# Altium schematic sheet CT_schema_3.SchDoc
size 283 x 147 mm
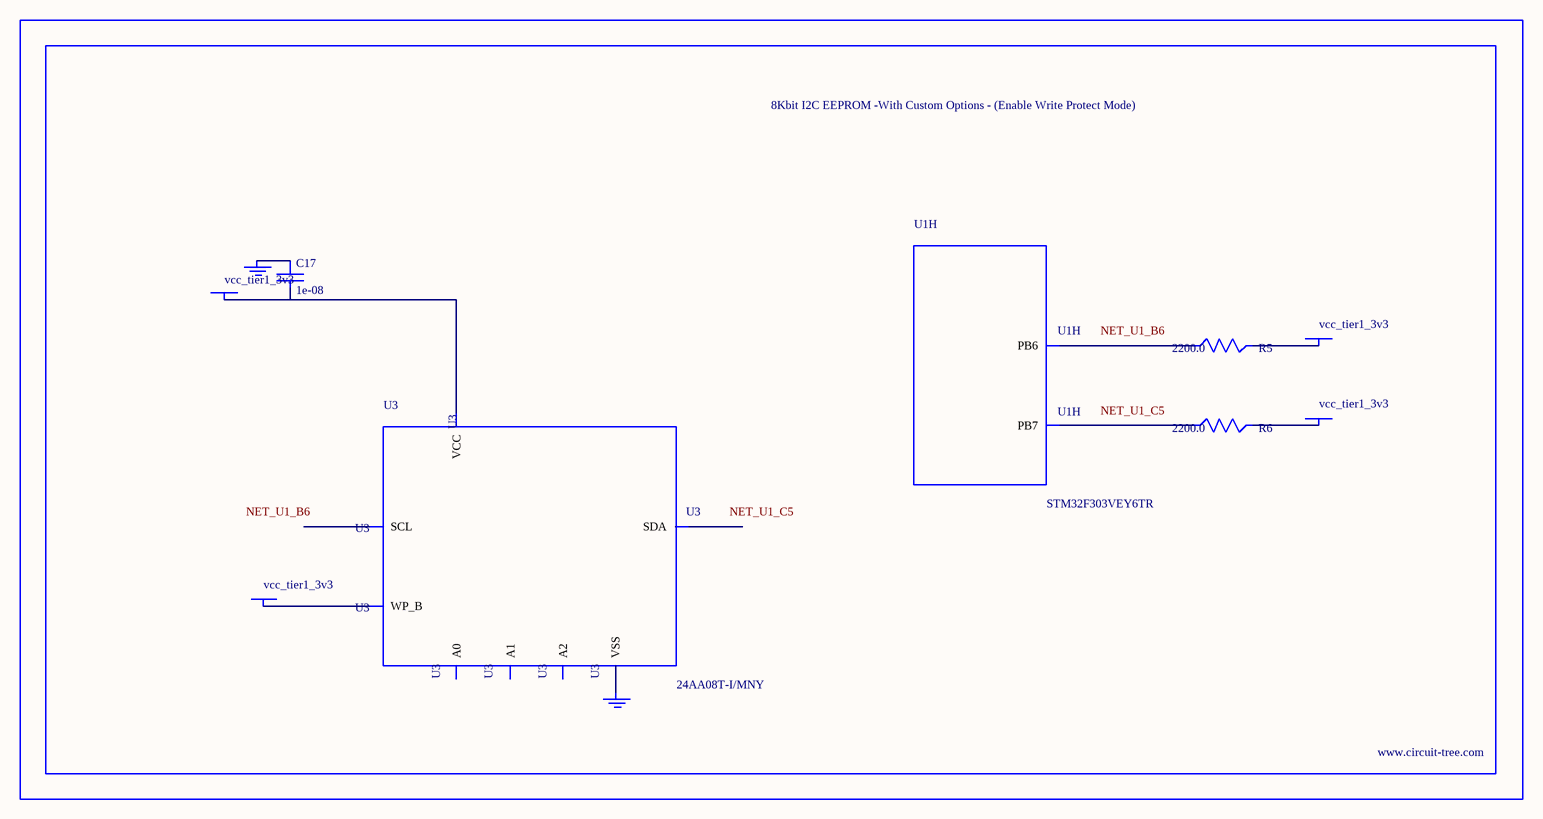
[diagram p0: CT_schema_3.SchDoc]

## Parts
BORDER2  (no value)
C17  1e-08  [C0402]
GND_INSTANCE_2_0  (no value)
GND_INSTANCE_2_1  (no value)
POWER_INSTANCE_2_0  vcc_tier1_3v3
POWER_INSTANCE_2_1  vcc_tier1_3v3
POWER_INSTANCE_2_2  vcc_tier1_3v3
POWER_INSTANCE_2_3  vcc_tier1_3v3
R5  2200.0  [R0603]
R6  2200.0  [R0603]
U1  STM32F303VEY6TR  [WLCSP100]  (part H of 9)
U3  24AA08T-I/MNY  [TDFN-8/6MM]

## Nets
NetC17_1: C17.1 GND_INSTANCE_2_0.0(GND)
NetC17_2: C17.2 POWER_INSTANCE_2_1.0(PWR) U3.8(VCC)
NetGND_INSTANCE_2_1_0: GND_INSTANCE_2_1.0(GND) U3.4(VSS)
NetPOWER_INSTANCE_2_0_0: POWER_INSTANCE_2_0.0(PWR) U3.7(WP_B)
NetPOWER_INSTANCE_2_2_0: POWER_INSTANCE_2_2.0(PWR) R5.2
NetPOWER_INSTANCE_2_3_0: POWER_INSTANCE_2_3.0(PWR) R6.2
NetR5_1: R5.1 U1.B6(PB6)
NetR6_1: R6.1 U1.C5(PB7)

Not connected (* = marked no-connect by the designer): U3 1(A0) 2(A1) 3(A2) 5(SDA) 6(SCL)

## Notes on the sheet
- Labels drawn without touching a wire or pin: NET_U1_B6, NET_U1_C5

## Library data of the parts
BORDER2 = BORDER_PAGE2
C17 = C0402C103K3RAC
GND_INSTANCE_2_0 GND_INSTANCE_2_1 = GND
POWER_INSTANCE_2_0-POWER_INSTANCE_2_3 = PWR
R5 R6 = RC0603JR-072K2L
